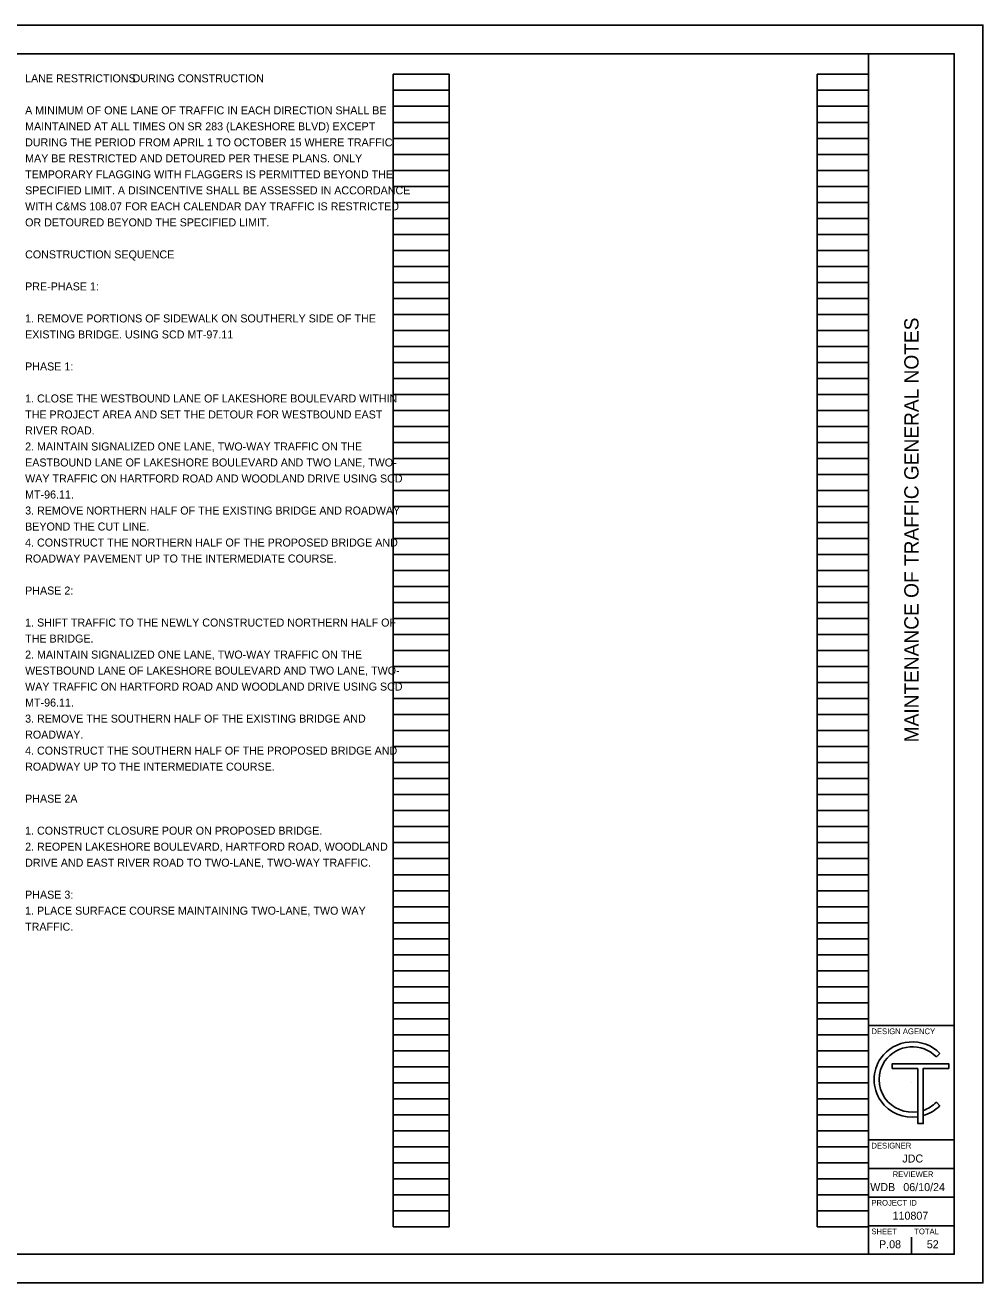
# Model space of a CAD drawing. Extents: x 0 to 34, y 0 to 22.
# Drawn here: x 17.24 to 34, y 0 to 22 of the extents above; entities that cross this region are included whole.
import ezdxf

# ---------------------------------------------------------------- set-up
doc = ezdxf.new("R2010")
doc.units = 0
for name, color, linetype in [('SH_Border', 7, 'Continuous'), ('SH_Cut_Line', 7, 'Continuous'), ('SH_Data', 7, 'Continuous'), ('SH_Text', 7, 'Continuous')]:
    doc.layers.add(name, color=color, linetype=linetype)

msp = doc.modelspace()

# ---------------------------------------------------------------- linework, layer by layer
at = {"layer": 'SH_Border'}
for p, q in [((32, 0.5), (32, 21.5)), ((32, 4.5), (33.5, 4.5)), ((32, 2.5), (33.5, 2.5)), ((32, 2), (33.5, 2)), ((32, 1.5), (33.5, 1.5)), ((32, 1), (33.5, 1))]:
    msp.add_line(p, q, dxfattribs=at)
msp.add_lwpolyline([(1.5, 21.5), (33.5, 21.5), (33.5, 0.5), (1.5, 0.5)], close=True, dxfattribs=at)
at = {"layer": 'SH_Cut_Line'}
msp.add_lwpolyline([(0, 0), (34, 0), (34, 22), (0, 22)], close=True, dxfattribs=at)
at = {"layer": 'SH_Data'}
for p, q in [((23.68, 0.98), (23.68, 21.14)), ((23.68, 21.14), (24.66, 21.14)), ((24.66, 0.98), (24.66, 21.14)), ((31.1, 0.98), (31.1, 21.14)), ((31.1, 21.14), (32, 21.14)), ((32, 0.98), (32, 21.14)), ((23.68, 20.86), (24.66, 20.86)), ((31.1, 20.86), (32, 20.86)), ((23.68, 20.58), (24.66, 20.58)), ((31.1, 20.58), (32, 20.58)), ((23.68, 20.3), (24.66, 20.3)), ((31.1, 20.3), (32, 20.3)), ((23.68, 20.02), (24.66, 20.02)), ((31.1, 20.02), (32, 20.02)), ((23.68, 19.74), (24.66, 19.74)), ((31.1, 19.74), (32, 19.74)), ((23.68, 19.46), (24.66, 19.46)), ((31.1, 19.46), (32, 19.46)), ((23.68, 19.18), (24.66, 19.18)), ((31.1, 19.18), (32, 19.18)), ((23.68, 18.9), (24.66, 18.9)), ((31.1, 18.9), (32, 18.9)), ((23.68, 18.62), (24.66, 18.62)), ((31.1, 18.62), (32, 18.62)), ((23.68, 18.34), (24.66, 18.34)), ((31.1, 18.34), (32, 18.34)), ((23.68, 18.06), (24.66, 18.06)), ((31.1, 18.06), (32, 18.06)), ((23.68, 17.78), (24.66, 17.78)), ((31.1, 17.78), (32, 17.78)), ((23.68, 17.5), (24.66, 17.5)), ((31.1, 17.5), (32, 17.5)), ((23.68, 17.22), (24.66, 17.22)), ((31.1, 17.22), (32, 17.22)), ((23.68, 16.94), (24.66, 16.94)), ((31.1, 16.94), (32, 16.94)), ((23.68, 16.66), (24.66, 16.66)), ((31.1, 16.66), (32, 16.66)), ((23.68, 16.38), (24.66, 16.38)), ((31.1, 16.38), (32, 16.38)), ((23.68, 16.1), (24.66, 16.1)), ((31.1, 16.1), (32, 16.1)), ((23.68, 15.82), (24.66, 15.82)), ((31.1, 15.82), (32, 15.82)), ((23.68, 15.54), (24.66, 15.54)), ((31.1, 15.54), (32, 15.54)), ((23.68, 15.26), (24.66, 15.26)), ((31.1, 15.26), (32, 15.26)), ((23.68, 14.98), (24.66, 14.98)), ((31.1, 14.98), (32, 14.98)), ((23.68, 14.7), (24.66, 14.7)), ((31.1, 14.7), (32, 14.7)), ((23.68, 14.42), (24.66, 14.42)), ((31.1, 14.42), (32, 14.42)), ((23.68, 14.14), (24.66, 14.14)), ((31.1, 14.14), (32, 14.14)), ((23.68, 13.86), (24.66, 13.86)), ((31.1, 13.86), (32, 13.86)), ((23.68, 13.58), (24.66, 13.58)), ((31.1, 13.58), (32, 13.58)), ((23.68, 13.3), (24.66, 13.3)), ((31.1, 13.3), (32, 13.3)), ((23.68, 13.02), (24.66, 13.02)), ((31.1, 13.02), (32, 13.02)), ((23.68, 12.74), (24.66, 12.74)), ((31.1, 12.74), (32, 12.74)), ((23.68, 12.46), (24.66, 12.46)), ((31.1, 12.46), (32, 12.46)), ((23.68, 12.18), (24.66, 12.18)), ((31.1, 12.18), (32, 12.18)), ((23.68, 11.9), (24.66, 11.9)), ((31.1, 11.9), (32, 11.9)), ((23.68, 11.62), (24.66, 11.62)), ((31.1, 11.62), (32, 11.62)), ((23.68, 11.34), (24.66, 11.34)), ((31.1, 11.34), (32, 11.34)), ((23.68, 11.06), (24.66, 11.06)), ((31.1, 11.06), (32, 11.06)), ((23.68, 10.78), (24.66, 10.78)), ((31.1, 10.78), (32, 10.78)), ((23.68, 10.5), (24.66, 10.5)), ((31.1, 10.5), (32, 10.5)), ((23.68, 10.22), (24.66, 10.22)), ((31.1, 10.22), (32, 10.22)), ((23.68, 9.94), (24.66, 9.94)), ((31.1, 9.94), (32, 9.94)), ((23.68, 9.66), (24.66, 9.66)), ((31.1, 9.66), (32, 9.66)), ((23.68, 9.38), (24.66, 9.38)), ((31.1, 9.38), (32, 9.38)), ((23.68, 9.1), (24.66, 9.1)), ((31.1, 9.1), (32, 9.1)), ((23.68, 8.82), (24.66, 8.82)), ((31.1, 8.82), (32, 8.82)), ((23.68, 8.54), (24.66, 8.54)), ((31.1, 8.54), (32, 8.54)), ((23.68, 8.26), (24.66, 8.26)), ((31.1, 8.26), (32, 8.26)), ((23.68, 7.98), (24.66, 7.98)), ((31.1, 7.98), (32, 7.98)), ((23.68, 7.7), (24.66, 7.7)), ((31.1, 7.7), (32, 7.7)), ((23.68, 7.42), (24.66, 7.42)), ((31.1, 7.42), (32, 7.42)), ((23.68, 7.14), (24.66, 7.14)), ((31.1, 7.14), (32, 7.14)), ((23.68, 6.86), (24.66, 6.86)), ((31.1, 6.86), (32, 6.86)), ((23.68, 6.58), (24.66, 6.58)), ((31.1, 6.58), (32, 6.58)), ((23.68, 6.3), (24.66, 6.3)), ((31.1, 6.3), (32, 6.3)), ((23.68, 6.02), (24.66, 6.02)), ((31.1, 6.02), (32, 6.02)), ((23.68, 5.74), (24.66, 5.74)), ((31.1, 5.74), (32, 5.74)), ((23.68, 5.46), (24.66, 5.46)), ((31.1, 5.46), (32, 5.46)), ((23.68, 5.18), (24.66, 5.18)), ((31.1, 5.18), (32, 5.18)), ((23.68, 4.9), (24.66, 4.9)), ((31.1, 4.9), (32, 4.9)), ((23.68, 4.62), (24.66, 4.62)), ((31.1, 4.62), (32, 4.62)), ((23.68, 4.34), (24.66, 4.34)), ((31.1, 4.34), (32, 4.34)), ((23.68, 4.06), (24.66, 4.06)), ((31.1, 4.06), (32, 4.06)), ((23.68, 3.78), (24.66, 3.78)), ((31.1, 3.78), (32, 3.78)), ((23.68, 3.5), (24.66, 3.5)), ((31.1, 3.5), (32, 3.5)), ((32.75, 3.5), (32.75, 3.5)), ((23.68, 3.22), (24.66, 3.22)), ((31.1, 3.22), (32, 3.22)), ((23.68, 2.94), (24.66, 2.94)), ((31.1, 2.94), (32, 2.94)), ((23.68, 2.66), (24.66, 2.66)), ((31.1, 2.66), (32, 2.66)), ((23.68, 2.38), (24.66, 2.38)), ((31.1, 2.38), (32, 2.38)), ((23.68, 2.1), (24.66, 2.1)), ((31.1, 2.1), (32, 2.1)), ((23.68, 1.82), (24.66, 1.82)), ((31.1, 1.82), (32, 1.82)), ((23.68, 1.54), (24.66, 1.54)), ((31.1, 1.54), (32, 1.54)), ((23.68, 1.26), (24.66, 1.26)), ((31.1, 1.26), (32, 1.26)), ((23.68, 0.98), (24.66, 0.98)), ((31.1, 0.98), (32, 0.98)), ((32.375, 0.675), (32.375, 0.675)), ((32.75, 0.5), (32.75, 0.8))]:
    msp.add_line(p, q, dxfattribs=at)
at = {"layer": 'SH_Text'}
for p, q in [((33.249, 4.013), (33.187, 3.952)), ((33.249, 4.013), (33.187, 3.952)), ((33.402, 3.833), (32.414, 3.833)), ((32.414, 3.833), (32.414, 3.751)), ((32.414, 3.751), (32.863, 3.751)), ((32.863, 3.751), (32.863, 2.785)), ((32.956, 2.785), (32.956, 3.751)), ((32.956, 3.751), (33.402, 3.751)), ((33.402, 3.751), (33.402, 3.833)), ((33.187, 3.16), (33.249, 3.099)), ((33.187, 3.16), (33.249, 3.099)), ((32.863, 2.993), (32.863, 2.905)), ((32.863, 2.993), (32.863, 2.905)), ((32.956, 2.925), (32.956, 3.016)), ((32.956, 2.925), (32.956, 3.016)), ((32.863, 2.785), (32.956, 2.785))]:
    msp.add_line(p, q, dxfattribs=at)
msp.add_lwpolyline([(32.863, 3.751), (32.863, 2.785), (32.956, 2.785), (32.956, 3.751), (33.402, 3.751), (33.402, 3.833), (32.414, 3.833), (32.414, 3.751)], close=True, dxfattribs=at)
for centre, radius, start, end in [((32.766, 3.535), 0.68, 44.7027, 144.3276), ((32.766, 3.535), 0.68, 44.7027, 144.3276), ((32.766, 3.535), 0.593, 44.7362, 144.1102), ((32.766, 3.535), 0.593, 44.7362, 144.1102), ((32.764, 3.556), 0.666, 145.7329, 214.2671), ((32.764, 3.556), 0.666, 145.7329, 214.2671), ((32.764, 3.556), 0.579, 145.7266, 214.2734), ((32.764, 3.556), 0.579, 145.7266, 214.2734), ((32.766, 3.578), 0.68, 215.6724, 278.2613), ((32.766, 3.578), 0.68, 215.6724, 278.2613), ((32.766, 3.578), 0.593, 215.8898, 279.4882), ((32.766, 3.578), 0.593, 215.8898, 279.4882), ((32.766, 3.578), 0.593, 288.6992, 315.2638), ((32.766, 3.578), 0.593, 288.6992, 315.2638), ((32.766, 3.578), 0.68, 286.2291, 315.2973), ((32.766, 3.578), 0.68, 286.2291, 315.2973)]:
    msp.add_arc(centre, radius, start, end, dxfattribs=at)

# ---------------------------------------------------------------- texts
at = {"layer": 'SH_Data'}
msp.add_text('MAINTENANCE OF TRAFFIC GENERAL NOTES', height=0.25, rotation=90, dxfattribs=at).set_placement((32.875, 9.455))
for s, height, p in [('DESIGN AGENCY', 0.1, (32.05, 4.35)), ('DESIGNER', 0.1, (32.05, 2.35)), ('JDC', 0.14, (32.591, 2.105)), ('REVIEWER', 0.1, (32.422, 1.85)), ('WDB', 0.14, (32.029, 1.605)), ('06/10/24', 0.14, (32.608, 1.605)), ('PROJECT ID', 0.1, (32.05, 1.35)), ('110807', 0.14, (32.42, 1.105)), ('SHEET', 0.1, (32.05, 0.85)), ('TOTAL', 0.1, (32.8, 0.85)), ('P.08', 0.14, (32.183, 0.605)), ('52', 0.14, (33.019, 0.605))]:
    msp.add_text(s, height=height, dxfattribs=at).set_placement(p)
at = {"layer": 'SH_Text'}
for s, p in [('LANE RESTRICTIONS', (17.24, 21)), ('DURING CONSTRUCTION', (19.12, 21)), ('A MINIMUM OF ONE LANE OF TRAFFIC IN EACH DIRECTION SHALL BE ', (17.24, 20.44)), ('MAINTAINED AT ALL TIMES ON SR 283 (LAKESHORE BLVD) EXCEPT ', (17.24, 20.16)), ('DURING THE PERIOD FROM APRIL 1 TO OCTOBER 15\xa0WHERE TRAFFIC ', (17.24, 19.88)), ('MAY BE RESTRICTED AND DETOURED PER THESE PLANS. ONLY ', (17.24, 19.6)), ('TEMPORARY FLAGGING WITH FLAGGERS IS PERMITTED BEYOND THE ', (17.24, 19.32)), ('SPECIFIED LIMIT. A DISINCENTIVE SHALL BE ASSESSED IN ACCORDANCE ', (17.24, 19.04)), ('WITH C&MS 108.07 FOR EACH CALENDAR DAY TRAFFIC IS RESTRICTED ', (17.24, 18.76)), ('OR DETOURED BEYOND THE SPECIFIED LIMIT.', (17.24, 18.48)), ('CONSTRUCTION SEQUENCE', (17.24, 17.92)), ('PRE-PHASE 1:', (17.24, 17.36)), ('1. REMOVE PORTIONS OF SIDEWALK ON SOUTHERLY SIDE OF THE ', (17.24, 16.8)), ('EXISTING BRIDGE. USING SCD MT-97.11', (17.24, 16.52)), ('PHASE 1:', (17.24, 15.96)), ('1. CLOSE THE WESTBOUND LANE OF LAKESHORE BOULEVARD WITHIN ', (17.24, 15.4)), ('THE PROJECT AREA AND SET THE DETOUR FOR WESTBOUND EAST ', (17.24, 15.12)), ('RIVER ROAD.', (17.24, 14.84)), ('2. MAINTAIN SIGNALIZED ONE LANE, TWO-WAY TRAFFIC ON THE ', (17.24, 14.56)), ('EASTBOUND LANE OF LAKESHORE BOULEVARD AND TWO LANE, TWO-', (17.24, 14.28)), ('WAY TRAFFIC ON HARTFORD ROAD AND WOODLAND DRIVE USING SCD ', (17.24, 14)), ('MT-96.11.', (17.24, 13.72)), ('3. REMOVE NORTHERN HALF OF THE EXISTING BRIDGE AND ROADWAY ', (17.24, 13.44)), ('BEYOND THE CUT LINE.', (17.24, 13.16)), ('4. CONSTRUCT THE NORTHERN HALF OF THE PROPOSED BRIDGE AND ', (17.24, 12.88)), ('ROADWAY PAVEMENT UP TO THE INTERMEDIATE COURSE.', (17.24, 12.6)), ('PHASE 2:', (17.24, 12.04)), ('1. SHIFT TRAFFIC TO THE NEWLY CONSTRUCTED NORTHERN HALF OF ', (17.24, 11.48)), ('THE BRIDGE.', (17.24, 11.2)), ('2. MAINTAIN SIGNALIZED ONE LANE, TWO-WAY TRAFFIC ON THE ', (17.24, 10.92)), ('WESTBOUND LANE OF LAKESHORE BOULEVARD AND TWO LANE, TWO-', (17.24, 10.64)), ('WAY TRAFFIC ON HARTFORD ROAD AND WOODLAND DRIVE USING SCD ', (17.24, 10.36)), ('MT-96.11.', (17.24, 10.08)), ('3. REMOVE THE SOUTHERN HALF OF THE EXISTING BRIDGE AND ', (17.24, 9.8)), ('ROADWAY.', (17.24, 9.52)), ('4. CONSTRUCT THE SOUTHERN HALF OF THE PROPOSED BRIDGE AND ', (17.24, 9.24)), ('ROADWAY UP TO THE INTERMEDIATE COURSE.', (17.24, 8.96)), ('PHASE 2A', (17.24, 8.4)), ('1. CONSTRUCT CLOSURE POUR ON PROPOSED BRIDGE.', (17.24, 7.84)), ('2. REOPEN LAKESHORE BOULEVARD, HARTFORD ROAD, WOODLAND ', (17.24, 7.56)), ('DRIVE AND EAST RIVER ROAD TO TWO-LANE, TWO-WAY TRAFFIC.', (17.24, 7.28)), ('PHASE 3:', (17.24, 6.72)), ('1. PLACE SURFACE COURSE MAINTAINING TWO-LANE, TWO WAY ', (17.24, 6.44)), ('TRAFFIC.', (17.24, 6.16))]:
    msp.add_text(s, height=0.14, dxfattribs=at).set_placement(p)

doc.saveas('drawing.dxf')
